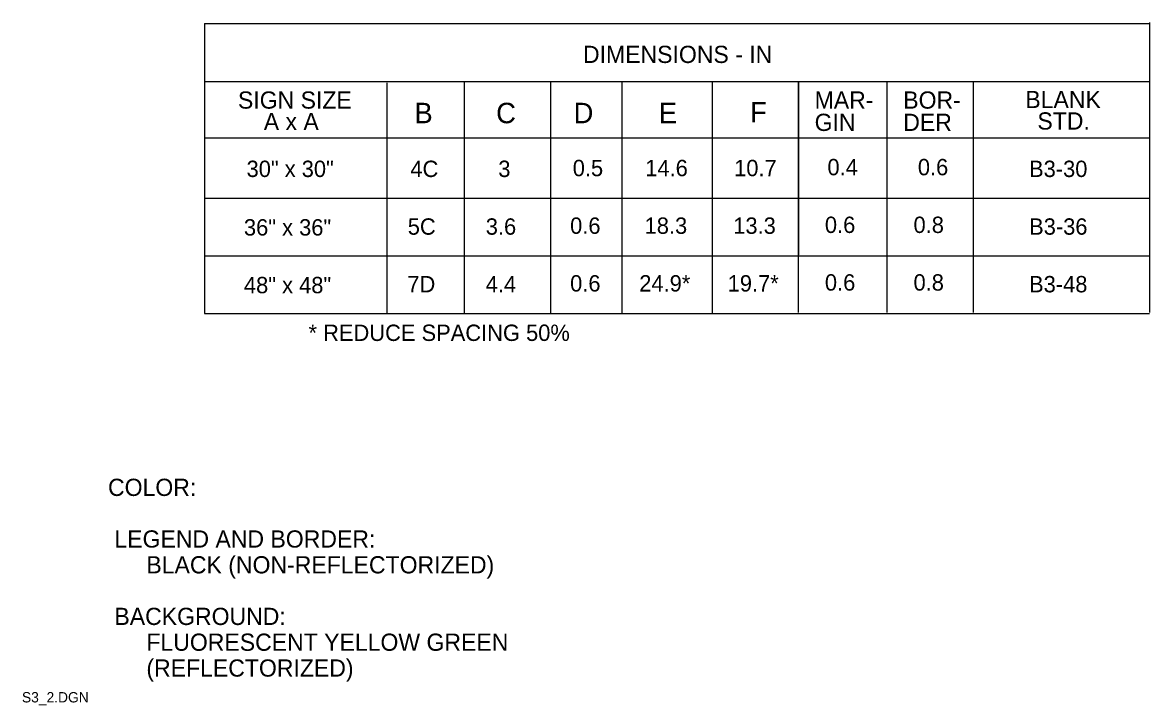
# Model space of a CAD drawing. Extents: x 0.013 to 0.191, y 0.004 to 0.259.
# Drawn here: x 0.0127 to 0.1764, y 0.0039 to 0.1031 of the extents above; entities that cross this region are included whole.
import ezdxf

# ---------------------------------------------------------------- set-up
doc = ezdxf.new("R2010")
doc.units = 0
doc.layers.add('1', color=7, linetype='Continuous')
doc.layers.add('3', color=7, linetype='Continuous')

msp = doc.modelspace()

# ---------------------------------------------------------------- linework, layer by layer
at = {"layer": '3'}
for p, q in [((0.17638, 0.10313), (0.17638, 0.061)), ((0.03913, 0.103), (0.17638, 0.103)), ((0.03913, 0.103), (0.03913, 0.06087)), ((0.17638, 0.0945), (0.03913, 0.0945)), ((0.06563, 0.09438), (0.06563, 0.06087)), ((0.07687, 0.0945), (0.07687, 0.06087)), ((0.08937, 0.0945), (0.08937, 0.06087)), ((0.09975, 0.0945), (0.09975, 0.06087)), ((0.11288, 0.0945), (0.11288, 0.06087)), ((0.12538, 0.0945), (0.12538, 0.061)), ((0.12542, 0.0945), (0.12542, 0.06937)), ((0.13825, 0.0945), (0.13825, 0.061)), ((0.15075, 0.09463), (0.15075, 0.061)), ((0.03913, 0.08638), (0.17638, 0.08638)), ((0.03913, 0.07762), (0.17638, 0.07762)), ((0.03913, 0.06925), (0.17638, 0.06925)), ((0.03913, 0.06087), (0.17638, 0.06087))]:
    msp.add_line(p, q, dxfattribs=at)

# ---------------------------------------------------------------- texts
at = {"layer": '1'}
for s, height, p in [('COLOR:', 0.0025, (0.02513, 0.03437)), (' LEGEND AND BORDER:', 0.0024998, (0.02513, 0.02687)), ('      BLACK (NON-REFLECTORIZED)', 0.0024998, (0.02513, 0.02312)), (' BACKGROUND:', 0.0024998, (0.02513, 0.01563)), ('      FLUORESCENT YELLOW GREEN', 0.0024998, (0.02513, 0.01188)), ('      (REFLECTORIZED)', 0.0024998, (0.02513, 0.00813)), ('S3_2.DGN', 0.0015, (0.01263, 0.00438))]:
    msp.add_text(s, height=height, dxfattribs=at).set_placement(p)
at = {"layer": '3'}
for s, height, p in [('DIMENSIONS - IN', 0.0024998, (0.09411, 0.09725)), ('SIGN SIZE', 0.0025, (0.044, 0.09062)), ('MAR-', 0.0025, (0.12775, 0.09062)), ('BOR-', 0.0025, (0.14062, 0.09062)), ('BLANK', 0.0025, (0.15835, 0.0907)), ('B', 0.00297, (0.06963, 0.0885)), ('C', 0.00297, (0.0815, 0.0885)), ('D', 0.00297, (0.09275, 0.0885)), ('E', 0.00297, (0.10512, 0.0885)), ('F', 0.00297, (0.11838, 0.08862)), ('STD.', 0.0025, (0.1601, 0.08758)), ('A x A', 0.0025, (0.04775, 0.0875)), ('GIN', 0.0025, (0.12775, 0.08738)), ('DER', 0.0025, (0.14062, 0.08738)), ('30" x 30"', 0.002375, (0.04525, 0.08069)), ('4C', 0.002375, (0.06904, 0.08069)), ('3', 0.00238, (0.08181, 0.08069)), ('0.5', 0.002375, (0.09262, 0.08081)), ('14.6', 0.002375, (0.10315, 0.08081)), ('10.7', 0.002375, (0.11606, 0.08081)), ('0.4', 0.002375, (0.12961, 0.08094)), ('0.6', 0.002375, (0.14274, 0.08094)), ('B3-30', 0.002375, (0.15889, 0.08069)), ('36" x 36"', 0.002375, (0.04487, 0.07219)), ('5C', 0.002375, (0.06866, 0.07231)), ('3.6', 0.002375, (0.07999, 0.07231)), ('0.6', 0.002375, (0.09224, 0.07244)), ('18.3', 0.002375, (0.10306, 0.07244)), ('13.3', 0.002375, (0.11593, 0.07244)), ('0.6', 0.002375, (0.12924, 0.07256)), ('0.8', 0.002375, (0.14211, 0.07256)), ('B3-36', 0.002375, (0.1589, 0.07231)), ('48" x 48"', 0.002375, (0.04487, 0.06381)), ('7D', 0.002375, (0.0686, 0.06394)), ('4.4', 0.002375, (0.07998, 0.06394)), ('0.6', 0.002375, (0.09224, 0.06406)), ('24.9*', 0.002375, (0.10228, 0.06406)), ('19.7*', 0.002375, (0.11512, 0.06406)), ('0.6', 0.002375, (0.12924, 0.06419)), ('0.8', 0.002375, (0.14211, 0.06419)), ('B3-48', 0.002375, (0.15889, 0.06394)), ('* REDUCE SPACING 50%', 0.0023752, (0.05425, 0.05688))]:
    msp.add_text(s, height=height, dxfattribs=at).set_placement(p)

doc.saveas('drawing.dxf')
